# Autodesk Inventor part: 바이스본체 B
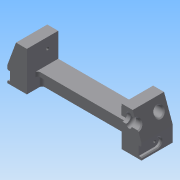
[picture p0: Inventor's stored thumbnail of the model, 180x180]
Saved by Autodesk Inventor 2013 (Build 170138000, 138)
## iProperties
Created: 2017-04
Part Number: 바이스본체 B
Material: 알루미늄 6061
Document SubType Name: Modeling
Designer: mduedu
Density: 2.71 g/cm^3
Mass: 246.705 g
Surface Area: 210.66 cm^2
Volume: 91.0351 cm^3
Author: mduedu
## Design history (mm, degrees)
sketch "스케치1"
  geometry: L1 (-75, 0)-(75, 0); L2 (-75, 0)-(-75, 17); L3 (-53, 17)-(53, 17); L4 (75, 17)-(75, 0); L5 (-75, 17)-(-65.173, 44); L6 (-65.173, 44)-(-53, 44); L7 (-53, 44)-(-53, 17); L8 (0, 0)-(0, 17); L9 (75, 17)-(65.173, 44); L10 (65.173, 44)-(53, 44); L11 (53, 44)-(53, 17); 1 further point
  constraints: 22 end point, 4 perpendicular, 2 horizontal alignment, 2 midpoint, 2 symmetric about line, 1 coincident, 1 collinear, 1 horizontal, 1 vertical
  dimensions: "d0" = 150 distance of L1.start L1.end; "d1" = 17 distance of L1.start L2.end; "d2" = 27 distance of L3.start L6.end; "d3" = 22 distance of L3.start L2.end; "d4" = 70 deg angle of L3 L5; "d54" = 20 deg angle of L9 L4
extrude "돌출1" new body sketch "스케치1" stored distance "d5" = 70; taper "d6" = 0 deg
sketch "스케치2"
  geometry: L1 (0, 70)-(106, 70) reference; L2 (106, 70)-(106, 0) reference; L3 (106, 0)-(0, 0) reference; L4 (0, 47)-(106, 47); L5 (106, 47)-(106, 23); L6 (106, 23)-(0, 23); L7 (0, 23)-(0, 47); L8 (0, 70)-(0, 0) reference; 2 further points
  constraints: 8 end point, 2 parallel, 2 point on line, 1 horizontal, 1 horizontal alignment, 1 midpoint, 1 perpendicular
  dimensions: "d7" = 24 distance between parallel lines of L6 L4
extrude "돌출2" cut sketch "스케치2" stored distance "d9" = 70; taper "d10" = 0 deg
sketch "스케치3"
  geometry: L1 (22, -23)-(128, -23) reference; L2 (128, -47)-(22, -47) reference; L3 (22, -18)-(128, -18); L4 (128, -52)-(22, -52); L5 (22, -18)-(22, -52); L6 (128, -18)-(128, -52); 1 further point
  constraints: 8 end point, 3 parallel, 2 point on line, 1 perpendicular
  dimensions: "d11" = 5 distance between parallel lines of L3 L1; "d12" = 5 distance between parallel lines of L4 L2
extrude "돌출3" cut sketch "스케치3" distance "d13" = 12; taper "d14" = 0 deg
fillet "모깎기1" dims "d15" = 3, "d16" = 3
sketch "스케치4"
  geometry: L1 (103, 23)-(3, 23) reference; L2 (0, 26)-(0, 0) reference; L3 (106, 0)-(0, 0) reference; L4 (106, 26)-(106, 0) reference; L5 (96, 0)-(90, 0); L6 (90, 0)-(90, 19.5); L7 (96, 19.5)-(96, 0); L8 (90, 19.5)-(96, 19.5); A1 r 3 centre (3, 26) between (0, 26) and (3, 23) reference; A2 r 3 centre (103, 26) between (103, 23) and (106, 26) reference; 1 further point
  constraints: 8 end point, 2 perpendicular, 1 horizontal, 1 parallel, 1 point on line
  dimensions: "d17" = 10 distance between parallel lines of L7 L4; "d18" = 6 distance between parallel lines of L7 L6; "d27" = 3.5 distance between parallel lines of L8 L1
extrude "돌출4" join sketch "스케치4" distance "d19" = 12; taper "d20" = 0 deg
chamfer "모따기1" distance "d21" = 3; stored, may be unused: second distance "d22" = 2, angle "d23" = 45 deg
chamfer "모따기2" distance "d24" = 3; stored, may be unused: second distance "d25" = 2, angle "d26" = 45 deg
sketch "스케치5"
  geometry: L1 (-15.5, 35.8)-(-15.5, -25.8) reference; L2 (19.5, 0)-(0, 0) reference; C1 r 6.5 at (9.5, 15); 1 further point
  constraints: 1 centre point
  dimensions: "d28" = 13 diameter of C1; "d30" = 15 distance from line of C1.centre L2; "d31" = 25 distance from line of C1.centre L1
extrude "돌출5" cut sketch "스케치5" stored distance "d32" = 12; taper "d33" = 0 deg
sketch "스케치6"
  geometry: C1 r 5 at (-10, 15); C2 r 5 at (-60, 15); A1 r 6.5 centre (-10, 15) between (-15.766, 12) and (-4.234, 12) reference; A2 r 6.5 centre (-60, 15) between (-65.766, 12) and (-54.234, 12) reference; 1 further point
  constraints: 2 centre point, 2 coincident
  dimensions: "d34" = 10 diameter of C1; "d35" = 10 diameter of C2 (= d34)
extrude "돌출6" cut sketch "스케치6" stored distance "d36" = 12; taper "d37" = 0 deg
chamfer "모따기3" distance "d38" = 1; stored, may be unused: second distance "d39" = 2, angle "d40" = 45 deg
chamfer "모따기4" distance "d41" = 1; stored, may be unused: second distance "d42" = 2, angle "d43" = 45 deg
sketch "스케치7"
  geometry: L1 (-35, 35.8)-(-35, -25.8) reference; L2 (-70, 0)-(0, 0) reference; C1 r 5 at (-35, 15); 1 further point
  constraints: 1 centre point, 1 point on line
  dimensions: "d44" = 10 diameter of C1; "d45" = 15 distance from line of C1.centre L2
extrude "돌출7" cut sketch "스케치7" stored distance "d46" = 12; taper "d47" = 0 deg
chamfer "모따기5" distance "d48" = 1; stored, may be unused: second distance "d49" = 2, angle "d50" = 45 deg
node "작업축1"
sketch "스케치8"
  geometry: L1 (-105, 32)-(105, 32) reference; L2 (58, 32)-(64, 32); L3 (64, 32)-(64, 40); L4 (64, 40)-(58, 40); L5 (58, 40)-(58, 32); L6 (53, 38)-(53, 26) reference; 1 further point
  constraints: 8 end point, 2 parallel, 1 horizontal, 1 perpendicular, 1 point on line
  dimensions: "d51" = 5 distance from line of L6 L2.start; "d52" = 6 distance of L3.end L4.end; "d53" = 16 diameter of L4 L1
revolve "회전1" sketch "스케치8" stored, may be unused: angle "d55" = 90 deg
fillet "모깎기2"
chamfer "모따기6" distance "d56" = 1; stored, may be unused: second distance "d57" = 2, angle "d58" = 45 deg
sketch "스케치9"
  geometry: L1 (17.5, 3)-(52.5, 3); L2 (52.5, 13)-(17.5, 13); L3 (70, 0)-(0, 0) reference; L4 (17.5, 8)-(52.5, 8); A1 r 5 centre (17.5, 8) between (17.5, 13) and (17.5, 3); A2 r 5 centre (52.5, 8) between (52.5, 3) and (52.5, 13); 3 further points
  constraints: 6 end point, 4 point on circle, 3 tangent, 2 centre point, 2 midpoint, 2 parallel, 1 horizontal, 1 vertical alignment
  dimensions: "d59" = 35 distance of L4.start L4.end; "d61" = 5 radius of A2; "d62" = 8 distance between parallel lines of L3 L4
extrude "돌출8" cut sketch "스케치9" distance "d63" = 3; taper "d64" = 0 deg
chamfer "모따기7" distance "d65" = 1; stored, may be unused: second distance "d66" = 2, angle "d67" = 45 deg
chamfer "모따기8" distance "d68" = 1; stored, may be unused: second distance "d69" = 2, angle "d70" = 45 deg
feature "분할1"
sketch "스케치10"
  geometry: A1 r 5 centre (0, 0) between (0, 5) and (0, -5) reference; 1 further point
  constraints: 1 coincident
hole "구멍1" sketch "스케치10" at (0, 0) diameter "d71" = 2.459; stored, may be unused: countersink angle "d75" = 90 deg, drill point angle "d77" = 120 deg; dims "d72" = 4.5, "d73" = 4, "d74" = 2, "d76" = 6
sketch "스케치11"
  geometry: L1 (0, 0)-(0, 27) reference; L2 (0, 27)-(-35, 27) reference; 2 further points
  dimensions: "d78" = 12 distance from line of point (-12, 15.5) L1; "d79" = 11.5 distance from line of point (-12, 15.5) L2
hole "구멍2" sketch "스케치11" at (-12, 15.5) diameter "d80" = 3.242; stored, may be unused: countersink angle "d84" = 90 deg, drill point angle "d86" = 120 deg; dims "d81" = 6, "d82" = 4, "d83" = 2, "d85" = 8
node "솔리드1"
mirror "대칭1"
mirror "대칭2"
mirror "대칭3"
mirror "대칭4"
node "투영된 루프1"
